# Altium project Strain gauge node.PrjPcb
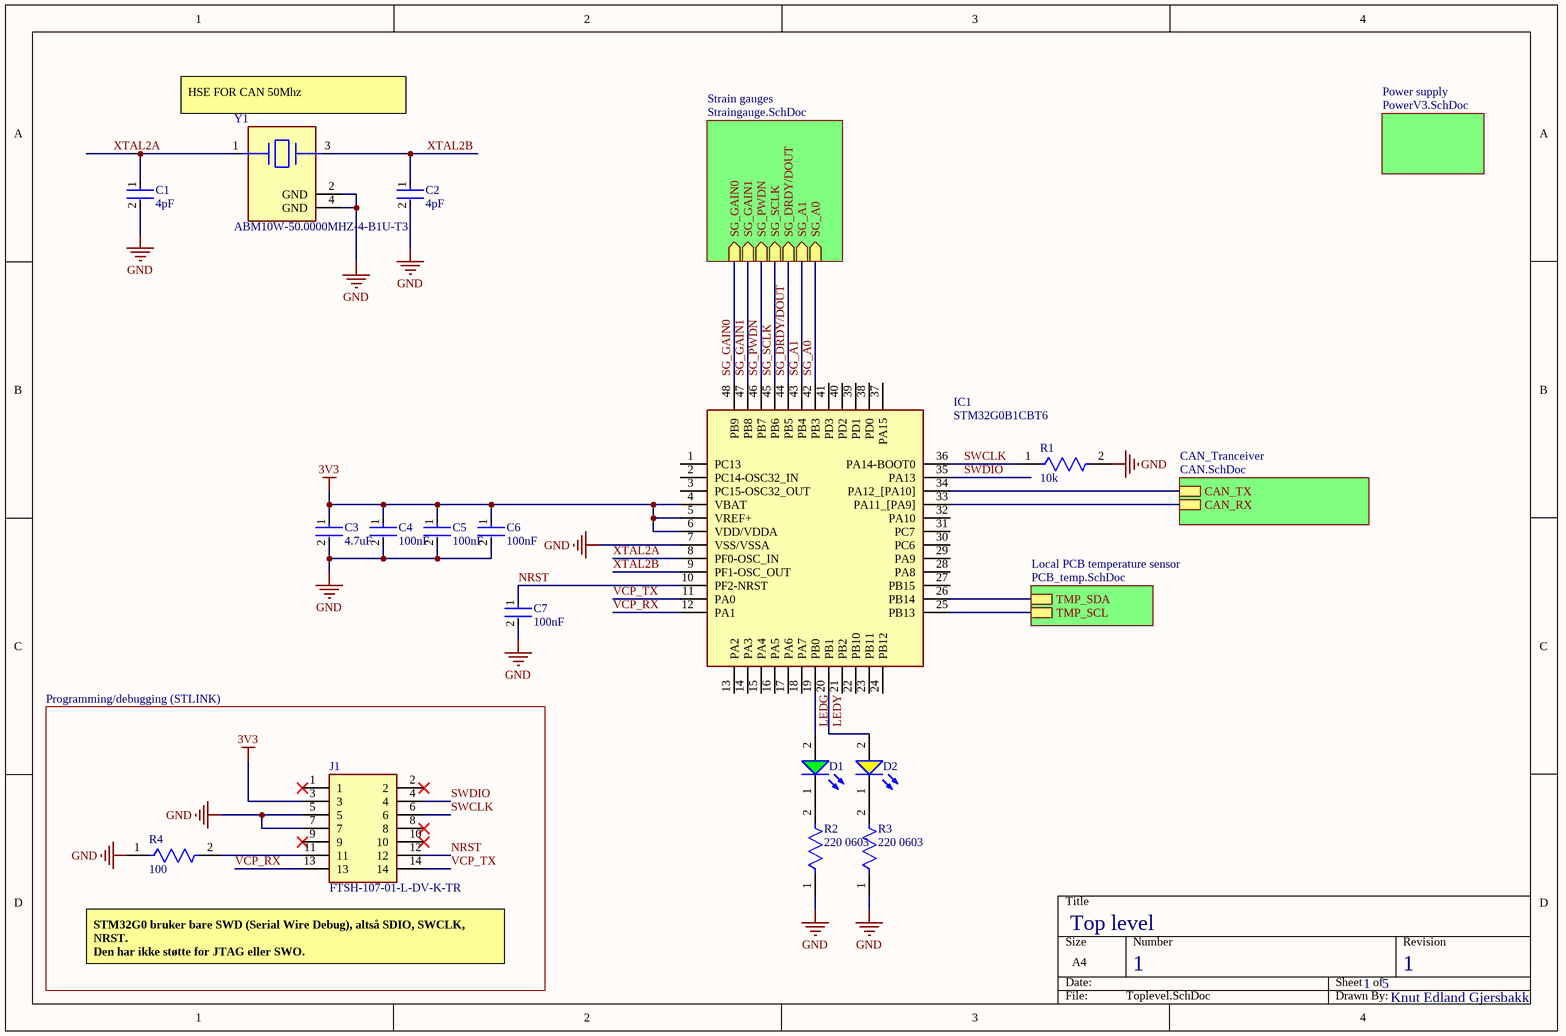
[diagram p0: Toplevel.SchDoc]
5 sheets, 79 parts. Net scope: hierarchical (ports join the sheet entries above them; power ports are global).
Board file: StrainNode.PcbDoc
Sheets:
  Toplevel.SchDoc
    Strain gauges = Straingauge.SchDoc
    Power supply = PowerV3.SchDoc
    CAN_Tranceiver = CAN.SchDoc
    Local PCB temperature sensor = PCB_temp.SchDoc

## Sheet Toplevel.SchDoc
size A4; SheetNumber: 1; SheetTotal: 5

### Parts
C1  4pF  [FP-GQM187-0_15-IPC_B]
C2  4pF  [FP-GQM187-0_15-IPC_B]
C3  4.7uF  [FP-GCM21B-0_15-IPC_A]
C4  100nF  [FP-CL10-IPC_A]
C5  100nF  [FP-CL10-IPC_A]
C6  100nF  [FP-CL10-IPC_A]
C7  100nF  [FP-CL10-IPC_A]
D1  150060GS55040  [WL-SMCD_0603]  (value not drawn)
D2  150060YS75020  [WL-SMCW_0603_150060xx75020]  (value not drawn)
IC1  STM32G0B1CBT6  [QFP50P900X900X160-48N]
J1  FTSH-107-01-L-DV-K-TR  [FTSH10701LDVKTR]
R1  10k  [FP-RT0603-IPC_C]
R2  220 0603  [FP-AF0603-IPC_C]
R3  220 0603  [FP-AF0603-IPC_C]
R4  100  [FP-RT0603-MFG]
Y1  ABM10W-50.0000MHZ-4-B1U-T3  [FP-ABM10W-MFG]

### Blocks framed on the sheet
Programming/debugging (STLINK): J1 R4

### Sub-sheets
CAN_Tranceiver = CAN.SchDoc: CAN_TX, CAN_RX
Local PCB temperature sensor = PCB_temp.SchDoc: TMP_SCL, TMP_SDA
Power supply = PowerV3.SchDoc: no entries
Strain gauges = Straingauge.SchDoc: SG_SCLK (in), SG_DRDY/DOUT (in), SG_PWDN (in), SG_GAIN1 (in), SG_GAIN0 (in), SG_A0 (in), SG_A1 (in)

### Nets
3V3: C3.1 C4.1 C5.1 C6.1 IC1.4(VBAT) IC1.5(VREF+) IC1.6(VDD/VDDA) J1.3
GND: C1.2 C2.2 C3.2 C4.2 C5.2 C6.2 C7.2 IC1.7(VSS/VSSA) J1.5 J1.7 R1.2 R2.1 R3.1 R4.1 Y1.2(GND) Y1.4(GND)
LEDG: D1.2(A) IC1.19(PB0)
LEDY: D2.2(A) IC1.20(PB1)
NRST: C7.1 IC1.10(PF2-NRST) J1.12
SCL: IC1.25(PB13) ; sheet Local PCB temperature sensor/TMP_SCL
SDA: IC1.26(PB14) ; sheet Local PCB temperature sensor/TMP_SDA
SG_A0: IC1.42(PB3) ; sheet Strain gauges/SG_A0
SG_A1: IC1.43(PB4) ; sheet Strain gauges/SG_A1
SG_DRDY/DOUT: IC1.44(PB5) ; sheet Strain gauges/SG_DRDY/DOUT
SG_GAIN0: IC1.48(PB9) ; sheet Strain gauges/SG_GAIN0
SG_GAIN1: IC1.47(PB8) ; sheet Strain gauges/SG_GAIN1
SG_PWDN: IC1.46(PB7) ; sheet Strain gauges/SG_PWDN
SG_SCLK: IC1.45(PB6) ; sheet Strain gauges/SG_SCLK
SWCLK: IC1.36(PA14-BOOT0) J1.6 R1.1
SWDIO: IC1.35(PA13) J1.4
VCP_RX: IC1.12(PA1) J1.13
VCP_TX: IC1.11(PA0) J1.14
XTAL2A: C1.1 IC1.8(PF0-OSC_IN) Y1.1
XTAL2B: C2.1 IC1.9(PF1-OSC_OUT) Y1.3
NetD1_1: D1.1(K) R2.2
NetD2_1: D2.1(K) R3.2
NetIC1_33: IC1.33(PA11_[PA9]) ; sheet CAN_Tranceiver/CAN_RX
NetIC1_34: IC1.34(PA12_[PA10]) ; sheet CAN_Tranceiver/CAN_TX
NetJ1_11: J1.11 R4.2

Not connected (* = marked no-connect by the designer): IC1 1(PC13) 2(PC14-OSC32_IN) 3(PC15-OSC32_OUT) 13(PA2) 14(PA3) 15(PA4) 16(PA5) 17(PA6) 18(PA7) 21(PB2) 22(PB10) 23(PB11) 24(PB12) 27(PB15) 28(PA8) 29(PA9) 30(PC6) 31(PC7) 32(PA10) 37(PA15) 38(PD0) 39(PD1) 40(PD2) 41(PD3); J1 1* 2* 8* 9* 10*

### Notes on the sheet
- (near Y1) HSE FOR CAN 50Mhz
- Top level
- STM32G0 bruker bare SWD (Serial Wire Debug), altså SDIO, SWCLK, NRST.
  Den har ikke støtte for JTAG eller SWO.
- 1
- 5
- Knut Edland Gjersbakk

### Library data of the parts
C1 C2 = CMP-06035-061124-1: GQM1875C2E4R0BB12D / Ceramic Capacitor 4pF ±0.1pF 250VDC C0G 0603 Paper T/R; Voltage Rating: 250V
C3 = CMP-2007-03343-2: Ceramic Capacitor for Automotive 4.7uF ±10% 16VDC X7R 0805 Embossed T/R; Voltage Rating (DC): 16V
C4-C7 = CMP-13271-002683-1: Cap Ceramic 100nF 16V X7R ±10% Pad SMD 0603 +125°C T/R
D1 = CMP-03913-90235563-2: 150060GS55040 WL-SMCD SMT Mono-color Chip LED Diffused; Forward Voltage: 3.2V; Forward Current: 60mA; Luminous Intensity: 430mcd; Peak Wavelength: 520nm; Viewing Angle: 140°; Wavelength: 525nm; Max Reverse Voltage (DC): 5V
D2 = CMP-03913-104891429-2: WL-SMCW SMT Mono-Color Chip LED Waterclear super f; Forward Voltage: 2V; Forward Current: 60mA; Max Reverse Voltage (DC): 5V; Peak Wavelength: 595nm; Viewing Angle: 140°; Dominant Wavelength: 590nm; Luminous Intensity: 130mcd
IC1 = STM32G0B1CBT6: Integrated Circuit; Manufacturer_Name: STMicroelectronics
J1 = FTSH-107-01-L-DV-K-TR: Connector; Manufacturer_Name: SAMTEC
R1 = CMP-03412-005349-1: RES SMD 10K OHM 1% 1/10W 0603 / RT0603FRE0710KL; Manufacturer: Yageo; Value: 10KΩ; Temperature Coefficient: 50 ppm/°C; Power Rating: 0.1W; Tolerance: 0.01; Voltage Rating: 75V
R2 R3 = CMP-03412-038529-1: AF0603JR-07220RL Anti-Sulfurated Chip Resistors Automotive Grade 220Ω 5% 100ppm/°C 0603; Max Power Dissipation: 100mW; Resistance: 220R
R4 = CMP-03412-030646-1: RT0603 100Ω 0.1W 50 ppm/°C 1.00% RT0603FRE07100RL; Manufacturer: Yageo; Manufacturer Part Number: RT0603FRE10100RL; Tolerance: 0.01; Voltage Rating: 75V
Y1 = CMP-27762-007472-1: Crystal 50MHz ±10ppm 4pF SMD-4 2.5mm x 2mm; ESR (Equivalent Series Resistance): 70R

## Sheet Straingauge.SchDoc
size A4; SheetNumber: 2; SheetTotal: 5
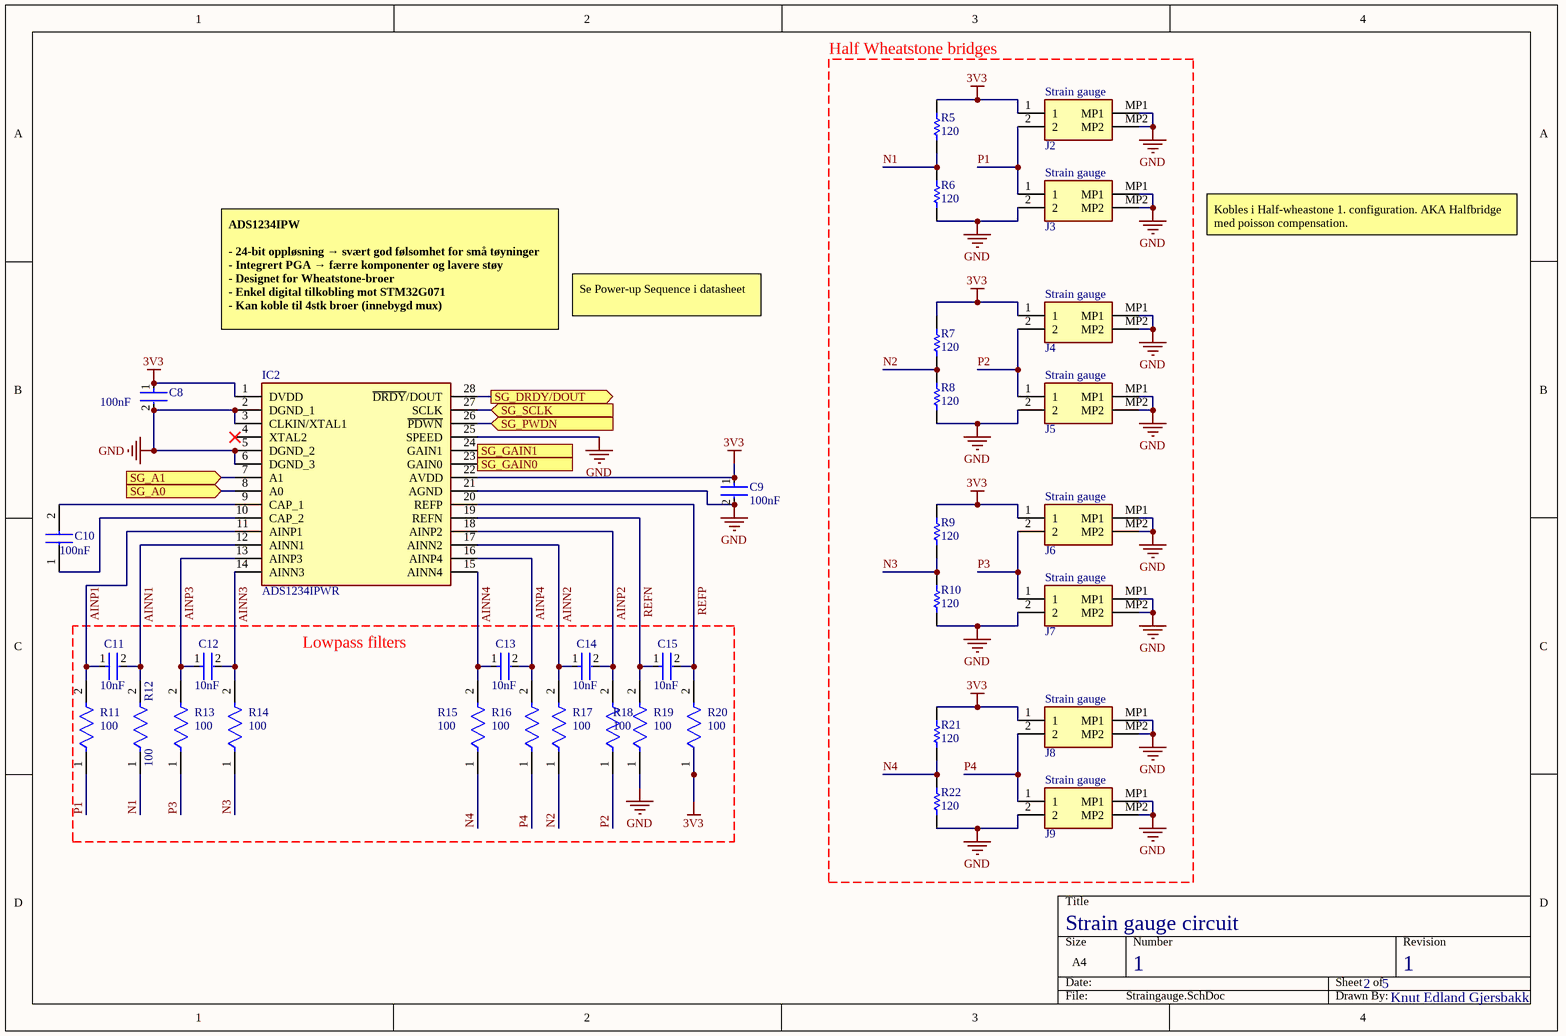
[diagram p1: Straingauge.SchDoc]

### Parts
C8  100nF  [FP-CL10-IPC_C]
C9  100nF  [FP-CL10-IPC_C]
C10  100nF  [CAPC3216X180N]
C11  Capacitance: 10nF  [FP-GRM219-0_1-IPC_B]  (hidden comment: GRM2195C1H103JA01D)
C12  Capacitance: 10nF  [FP-GRM219-0_1-IPC_B]  (hidden comment: GRM2195C1H103JA01D)
C13  Capacitance: 10nF  [FP-GRM219-0_1-IPC_B]  (hidden comment: GRM2195C1H103JA01D)
C14  Capacitance: 10nF  [FP-GRM219-0_1-IPC_B]  (hidden comment: GRM2195C1H103JA01D)
C15  Capacitance: 10nF  [FP-GRM219-0_1-IPC_B]  (hidden comment: GRM2195C1H103JA01D)
IC2  ADS1234IPWR  [SOP65P640X120-28N]
J2  S2B-PH-SM4-TB_LF__SN_  [S2BPHSM4TBLFSN]  (value not drawn)
J3  S2B-PH-SM4-TB_LF__SN_  [S2BPHSM4TBLFSN]  (value not drawn)
J4  S2B-PH-SM4-TB_LF__SN_  [S2BPHSM4TBLFSN]  (value not drawn)
J5  S2B-PH-SM4-TB_LF__SN_  [S2BPHSM4TBLFSN]  (value not drawn)
J6  S2B-PH-SM4-TB_LF__SN_  [S2BPHSM4TBLFSN]  (value not drawn)
J7  S2B-PH-SM4-TB_LF__SN_  [S2BPHSM4TBLFSN]  (value not drawn)
J8  S2B-PH-SM4-TB_LF__SN_  [S2BPHSM4TBLFSN]  (value not drawn)
J9  S2B-PH-SM4-TB_LF__SN_  [S2BPHSM4TBLFSN]  (value not drawn)
R5  120  [RESC2013X60X40ML20T25]
R6  120  [RESC2013X60X40ML20T25]
R7  120  [RESC2013X60X40ML20T25]
R8  120  [RESC2013X60X40ML20T25]
R9  120  [RESC2013X60X40ML20T25]
R10  120  [RESC2013X60X40ML20T25]
R11  100  [FP-ERA3A-IPC_B]
R12  100  [FP-ERA3A-IPC_B]
R13  100  [FP-ERA3A-IPC_B]
R14  100  [FP-ERA3A-IPC_B]
R15  100  [FP-ERA3A-IPC_B]
R16  100  [FP-ERA3A-IPC_B]
R17  100  [FP-ERA3A-IPC_B]
R18  100  [FP-ERA3A-IPC_B]
R19  100  [FP-ERA3A-IPC_B]
R20  100  [FP-ERA3A-IPC_B]
R21  120  [RESC2013X60X40ML20T25]
R22  120  [RESC2013X60X40ML20T25]

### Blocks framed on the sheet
Half Wheatstone bridges: J2-J9 R5-R10 R21 R22
Lowpass filters: C11-C15 R11-R20

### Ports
SG_A0 (in, see Toplevel[3B]), SG_A1 (in, see Toplevel[3B]), SG_DRDY/DOUT (out, see Toplevel[3B]), SG_GAIN0 (in, see Toplevel[2B]), SG_GAIN1 (in, see Toplevel[2B]), SG_PWDN (in, see Toplevel[2B]), SG_SCLK (in, see Toplevel[2B])

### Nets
3V3: C8.1 C9.1 IC2.1(DVDD) IC2.22(AVDD) J2.1 J4.1 J6.1 J8.1 R5.2 R7.2 R9.2 R20.1 R21.2
GND: C8.2 C9.2 IC2.2(DGND_1) IC2.3(CLKIN/XTAL1) IC2.5(DGND_2) IC2.6(DGND_3) IC2.21(AGND) IC2.25(SPEED) J2.MP1 J2.MP2 J3.2 J3.MP1 J3.MP2 J4.MP1 J4.MP2 J5.2 J5.MP1 J5.MP2 J6.MP1 J6.MP2 J7.2 J7.MP1 J7.MP2 J8.MP1 J8.MP2 J9.2 J9.MP1 J9.MP2 R6.1 R8.1 R10.1 R19.1 R22.1
AINN1: C11.2 IC2.12(AINN1) R12.2
AINN2: C14.1 IC2.17(AINN2) R17.2
AINN3: C12.2 IC2.14(AINN3) R14.2
AINN4: C13.1 IC2.15(AINN4) R15.2
AINP1: C11.1 IC2.11(AINP1) R11.2
AINP2: C14.2 IC2.18(AINP2) R18.2
AINP3: C12.1 IC2.13(AINP3) R13.2
AINP4: C13.2 IC2.16(AINP4) R16.2
N1: R5.1 R6.2 R12.1
N2: R7.1 R8.2 R17.1
N3: R9.1 R10.2 R14.1
N4: R15.1 R21.1 R22.2
P1: J2.2 J3.1 R11.1
P2: J4.2 J5.1 R18.1
P3: J6.2 J7.1 R13.1
P4: J8.2 J9.1 R16.1
REFN: C15.1 IC2.19(REFN) R19.2
REFP: C15.2 IC2.20(REFP) R20.2
SG_A0: IC2.8(A0) ; port SG_A0
SG_A1: IC2.7(A1) ; port SG_A1
SG_DRDY/DOUT: IC2.28(~{DRDY}/DOUT) ; port SG_DRDY/DOUT
SG_GAIN0: IC2.23(GAIN0) ; port SG_GAIN0
SG_GAIN1: IC2.24(GAIN1) ; port SG_GAIN1
SG_PWDN: IC2.26(~{PDWN}) ; port SG_PWDN
SG_SCLK: IC2.27(SCLK) ; port SG_SCLK
NetC10_1: C10.1 IC2.10(CAP_2)
NetC10_2: C10.2 IC2.9(CAP_1)

Not connected (* = marked no-connect by the designer): IC2 4(XTAL2)*

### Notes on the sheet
- (near J2) Strain gauge
- (near J3) Strain gauge
- Kobles i Half-wheastone 1. configuration. AKA Halfbridge med poisson compensation.
- Se Power-up Sequence i datasheet
- (near J4) Strain gauge
- ADS1234IPW
  - 24-bit oppløsning → svært god følsomhet for små tøyninger
  - Integrert PGA → færre komponenter og lavere støy
  - Designet for Wheatstone-broer
  - Enkel digital tilkobling mot STM32G071
  - Kan koble til 4stk broer (innebygd mux)
  Gain bør settes til 64 for Half bridge
- (near J5) Strain gauge
- (near J6) Strain gauge
- (near J7) Strain gauge
- (near J8) Strain gauge
- (near J9) Strain gauge
- Strain gauge circuit
- 1
- 2
- 5
- Knut Edland Gjersbakk

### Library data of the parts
C8 C9 = CMP-13271-002683-1: Cap Ceramic 100nF 16V X7R ±10% Pad SMD 0603 +125°C T/R / CL10B104KO8WPNC
C10 = GRM31C5C1E104JA01L: Capacitor; Manufacturer_Name: Murata Electronics
C11-C15 = CMP-2007-00135-2: Chip Multilayer Ceramic Capacitors for General Purpose, 0805, 10000pF, C0G, 30ppm/°C, 5%, 50V; Insulation Resistance: 10GR
IC2 = ADS1234IPWR: Integrated Circuit; Manufacturer_Name: Texas Instruments
J2-J9 = S2B-PH-SM4-TB_LF__SN_: Connector; Manufacturer_Name: JST (JAPAN SOLDERLESS TERMINALS); Manufacturer_Part_Number: S2B-PH-SM4-TB(LF)(SN)
R5-R10 R21 R22 = CMP-2001-00588-1: Manufacturer: Panasonic; Part Number: ERA6AEB121V
R11-R20 = CMP-2000-00870-2: RES SMD 100 OHM 0.1% 1/10W 0603; Voltage Rating: 75V; Power Rating: 100mW; Resistance: 100R; Temperature Coefficient: 25ppm/°C

## Sheet PowerV3.SchDoc
size A3; SheetNumber: 4; SheetTotal: 5
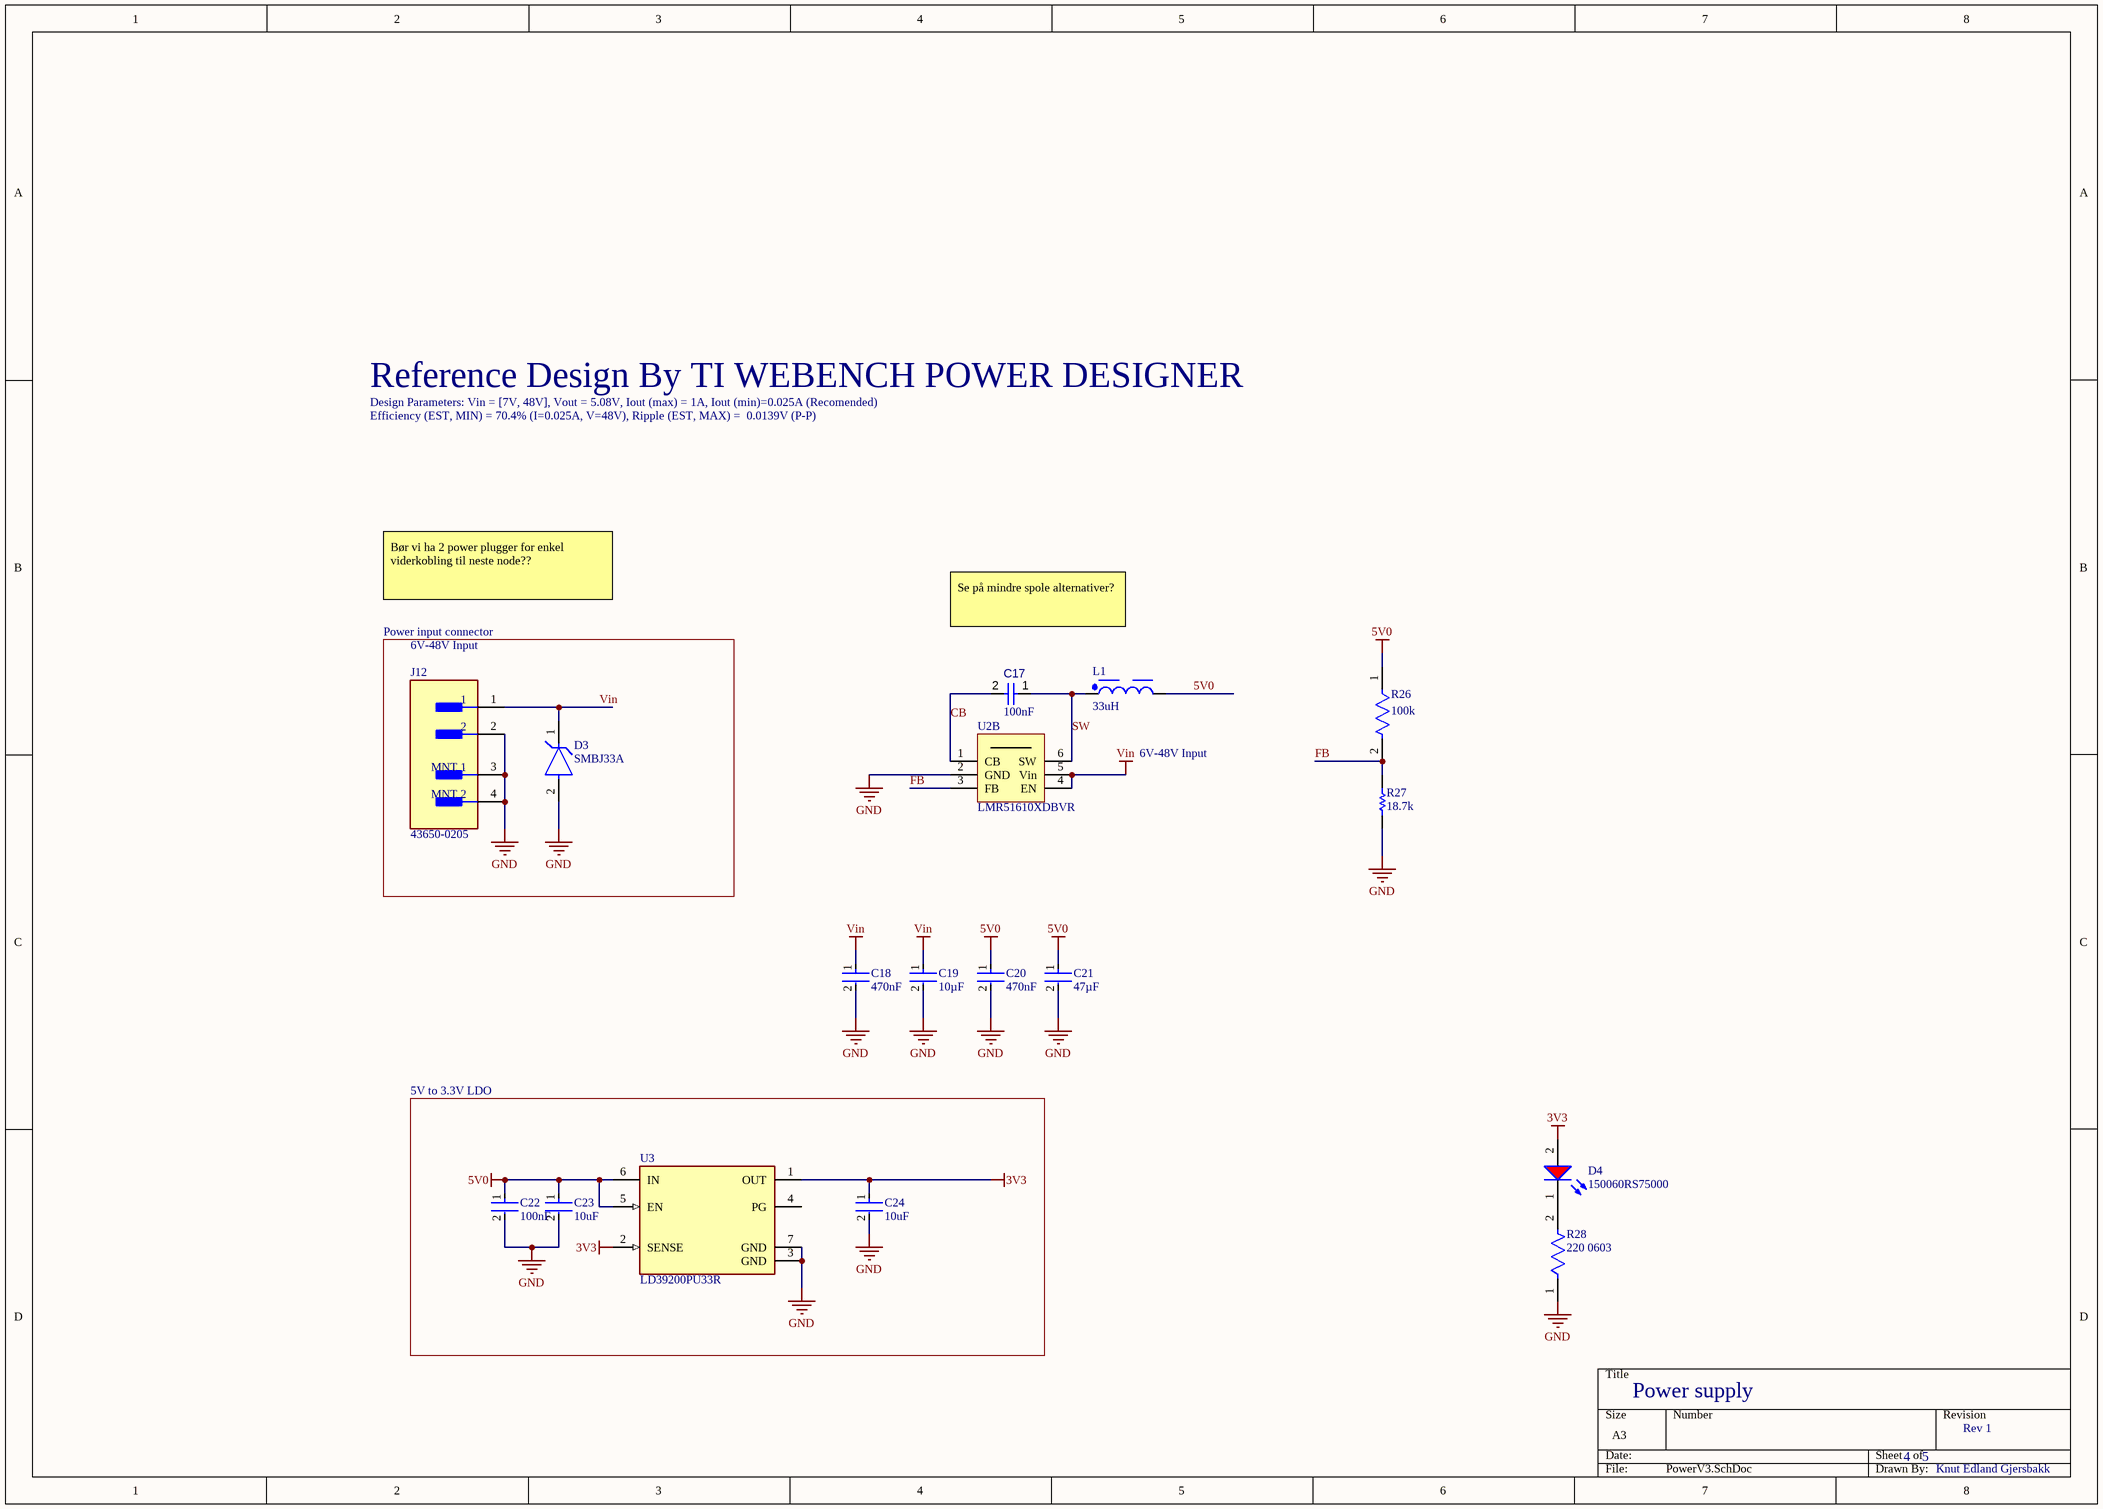
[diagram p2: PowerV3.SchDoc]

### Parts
C17  value 100nF  [CAPC2013X95X50LL10T25]  (hidden comment: Capacitor 100 nF +/-10% 50 V 0805)
C18  value 470nF  [FP-CL21-IPC_A]  (hidden comment: CL21B474KBFNNNF)
C19  value 10µF  [FP-CL31B106KBHNNNE-IPC_A]  (hidden comment: CL31B106KBHNNNE)
C20  value 470nF  [FP-CL21-IPC_A]  (hidden comment: CL21B474KBFNNNF)
C21  value 47µF  [FP-GRM31C-0_2-e0_3_0_8-IPC_B]  (hidden comment: GRM31CR61A476KE15K)
C22  100nF  [FP-CL10-IPC_C]
C23  10uF  [FP-CL10-IPC_C]
C24  10uF  [FP-CL10-IPC_C]
D3  SMBJ33A  [FP-SMBJ-MFG]
D4  150060RS75000  [WL-SMCW_0603_150060xx75000]
J12  43650-0205  [FP-43650-0205-MFG]
L1  value 33uH  [WE-PD_1260P]  (hidden comment: 7447706330)
R26  value 100k  [FP-CRGCQ1206-IPC_A]  (hidden comment: CRGCQ1206F100K)
R27  value 18.7k  [RESC2013X60X40LL20T25]  (hidden comment: ERA-6AEB1872V)
R28  220 0603  [FP-AF0603-IPC_C]
U2  LMR51610XDBVR  [SOT95P280X145-6N]  (part B of 2)
U3  LD39200PU33R  [FP-DFN6-7946637-MFG]

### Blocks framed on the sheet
5V to 3.3V LDO: C22-C24 U3

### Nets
3V3: C24.1 D4.2(A) U3.1(OUT) U3.2(SENSE)
5V0: C20.1 C21.1 C22.1 C23.1 L1.2 R26.1 U3.5(EN) U3.6(IN)
GND: C18.2 C19.2 C20.2 C21.2 C22.2 C23.2 C24.2 D3.2(A) J12.2 J12.3(MNT_1) J12.4(MNT_2) R27.2 R28.1 U2.2(GND) U3.3(GND) U3.7(GND)
Vin: C18.1 C19.1 D3.1(C) J12.1 U2.4(EN) U2.5(Vin)
CB: C17.2 U2.1(CB)
FB: R26.2 R27.1 U2.3(FB)
SW: C17.1 L1.1 U2.6(SW)
NetD4_1: D4.1(K) R28.2

Not connected (* = marked no-connect by the designer): U3 4(PG)

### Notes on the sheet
- Reference Design By TI WEBENCH POWER DESIGNER
- Design Parameters: Vin = [7V, 48V], Vout = 5.08V, Iout (max) = 1A, Iout (min)=0.025A (Recomended)
- Efficiency (EST, MIN) = 70.4% (I=0.025A, V=48V), Ripple (EST, MAX) =  0.0139V (P-P)
- Power input connector
- Bør vi ha 2 power plugger for enkel viderkobling til neste node??
- 6V-48V Input
- Se på mindre spole alternativer?
- Power supply
- 4
- 5
- Rev 1
- Knut Edland Gjersbakk

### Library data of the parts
C17 = CMP-001-00018-6: Chip Capacitor, 100 nF, +/- 10%, 50 V, 0805 (2012 Metric); Capacitor Type: Ceramic; Voltage Rating: 50V
C18 C20 = CMP-001-00098-1: Ceramic Capacitor, Multilayer, Ceramic, 50V, 10% +Tol, 10% -Tol, X7R, 15% TC, 0.47uF, Surface Mount, 0805; Multilayer: Yes
C19 = CMP-001-00099-1: Ceramic Capacitor, Multilayer, Ceramic, 50V, 10% +Tol, 10% -Tol, X7R, 15% TC, 10uF, Surface Mount, 1206; Multilayer: Yes
C21 = CMP-001-00103-1: Ceramic Capacitor, Multilayer, Ceramic, 10V, 10% +Tol, 10% -Tol, X5R, 15% TC, 47uF, Surface Mount, 1206; Multilayer: Yes
C22 = CMP-13271-002683-1: as C8 on sheet Straingauge
C23 C24 = CMP-13271-003287-1: Cap Ceramic 10uF 16V X6S ±20% Pad SMD 0603 +105°C T/R / CL10X106MO8NRNC
D3 = CMP-2000-07095-2: TVS DIODE 33V 53.3V DO214AA; Manufacturer: Littelfuse Inc; Max Junction Temp: +150°C; Number Of Channels: 1; Breakdown Voltage: 36.7V; Peak Pulse Power: 600W; Direction: Unidirectional; Peak Pulse Current: 11.3A
D4 = CMP-1426-00001-4: LED Low-Power Uni-Color Red 630nm 2V 2-Pin Chip 0603(1608Metric) T/R; Max Junction Temperature (Tj): 95°C; Dominant Wavelength: 625nm; Lens Style: Clear, Rectangular; Viewing Angle: 140°; Forward Current: 100mA; Max Reverse Voltage (DC): 5V; Luminous Intensity: 250mcd; Test Current: 20mA; Power Dissipation: 72mW
J12 = CMP-00257-07672643-1: 43650-0205 Conn Wire to Board HDR 2 POS 3mm Solder RA Side Entry Thru-Hole Micro-Fit 3.0™ Tray; Manufacturer Lifecycle Status: ACTIVE; Plating: Tin; Glow Wire Compliant: Compliant; Number of Contacts: 2; Gender: Male; Voltage Rating: 600V; Current Rating: 5A
L1 = CMP-006-00028-1: General Purpose Inductor
R26 = CMP-009-00192-1: Fixed Resistor, Metal Glaze/thick Film, 0.25W, 100000ohm, 200V, 1% +/-Tol, 100ppm/Cel, Surface Mount, 1206
R27 = CMP-009-00195-1: Fixed Resistor, Thin Film, 0.125W, 18700ohm, 100V, 0.1% +/-Tol, 25ppm/Cel, Surface Mount, 0805; Rated Temperature: 85°C; Temperature Coefficient (ppm/Cel): 25; Reference Standard: AEC-Q200; Package Width: 1.25mm; Package Length: 2mm; Package Height: 0.5mm; Power: 125mW
R28 = CMP-03412-038529-1: as R2 on sheet Toplevel
U2 = CMP-019-00059-1: SIMPLE SWITCHER® 4.5-V to 65-V, 1-A synchronous buck converter with 25-µA IQ 6-SOT-23 -40 to 150; Max Supply Voltage: 65V; Min Supply Voltage: 4.5V; Output Current: 1A; Frequency: 400Hz
U3 = CMP-12153-000011-1: IC REG LINEAR 3.3V 2A 6DFN; Number of Outputs: 1; Max Input Voltage: 6V; Output Type: Fixed; Min Input Voltage: 1.25V; Dropout Voltage: 130mV; Operating Supply Current: 1mA

## Sheet CAN.SchDoc
size A4; SheetNumber: 3; SheetTotal: 5
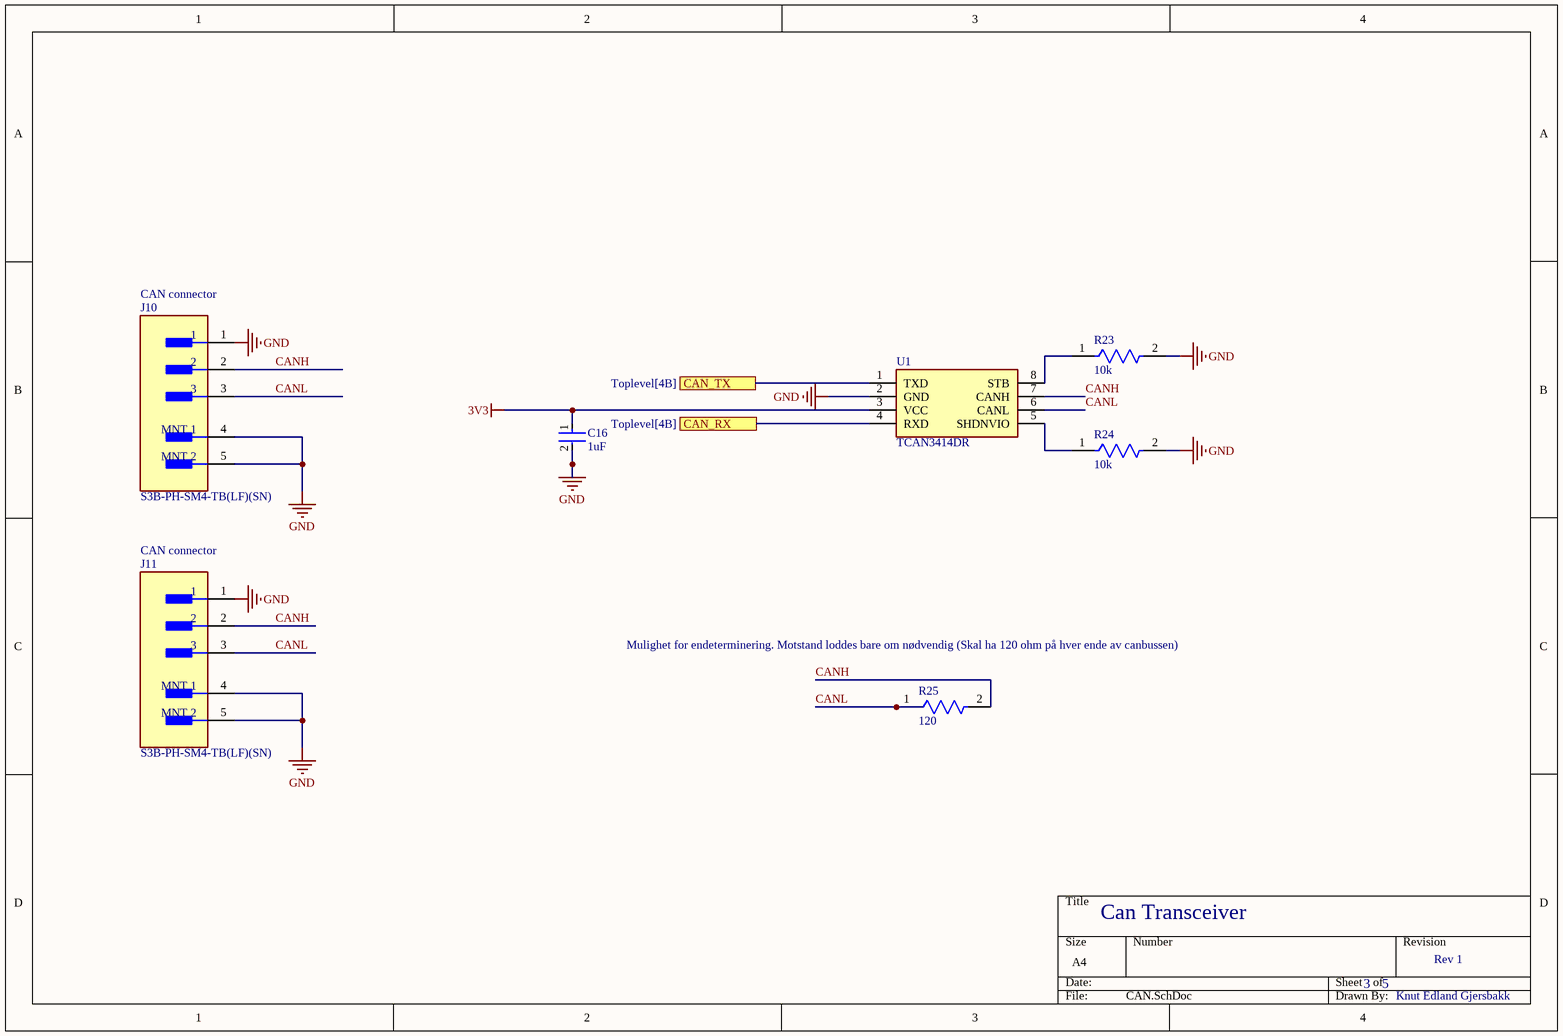
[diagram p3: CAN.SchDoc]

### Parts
C16  1uF  [FP-CL10-IPC_C]
J10  S3B-PH-SM4-TB(LF)(SN)  [FP-S3B-PH-SM4-TB_LF_SN-MFG]
J11  S3B-PH-SM4-TB(LF)(SN)  [FP-S3B-PH-SM4-TB_LF_SN-MFG]
R23  10k  [FP-RT0603-IPC_C]
R24  10k  [FP-RT0603-IPC_C]
R25  120  [FP-AF0603-IPC_C]
U1  TCAN3414DR  [SOIC127P600X175-8N]

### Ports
CAN_RX (see Toplevel[4B]), CAN_TX (see Toplevel[4B])

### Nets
3V3: C16.1 U1.3(VCC)
GND: C16.2 J10.1 J10.4(MNT_1) J10.5(MNT_2) J11.1 J11.4(MNT_1) J11.5(MNT_2) R23.2 R24.2 U1.2(GND)
CANH: J10.2 J11.2 R25.2 U1.7(CANH)
CANL: J10.3 J11.3 R25.1 U1.6(CANL)
NetIC1_33: U1.4(RXD) ; port CAN_RX
NetIC1_34: U1.1(TXD) ; port CAN_TX
NetR23_1: R23.1 U1.8(STB)
NetR24_1: R24.1 U1.5(SHDNVIO)

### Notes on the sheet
- (near J10) CAN connector
- (near J11) CAN connector
- Mulighet for endeterminering. Motstand loddes bare om nødvendig (Skal ha 120 ohm på hver ende av canbussen)
- Can Transceiver
- 3
- 5
- Rev 1
- Knut Edland Gjersbakk

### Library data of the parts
C16 = CMP-13271-000784-1: Cap Ceramic 1uF 16V X7R ±10% Pad SMD 0603 +125°C T/R / CL10B105KO8NNNL
J10 J11 = CMP-002-00113-1: Connector Header, PH Series, 3 Position, Side Entry, 2.00mm, Solder, Surface Mount, Natural.; Voltage Rating: 100V; Max Current Rating: 2A; Connector Type: Male Pin; Gender: Male
R23 R24 = CMP-03412-005349-1: as R1 on sheet Toplevel
R25 = CMP-03412-039700-1: Anti-Sulfurated Chip Resistors Automotive Grade 120Ω 1% 100ppm/°C 0603 AF0603FR-07120RL; Max Power Dissipation: 100mW; Resistance: 120R
U1 = TCAN3414DR: Integrated Circuit; Manufacturer_Name: Texas Instruments

## Sheet PCB_temp.SchDoc
size A4; SheetNumber: 5; SheetTotal: 5
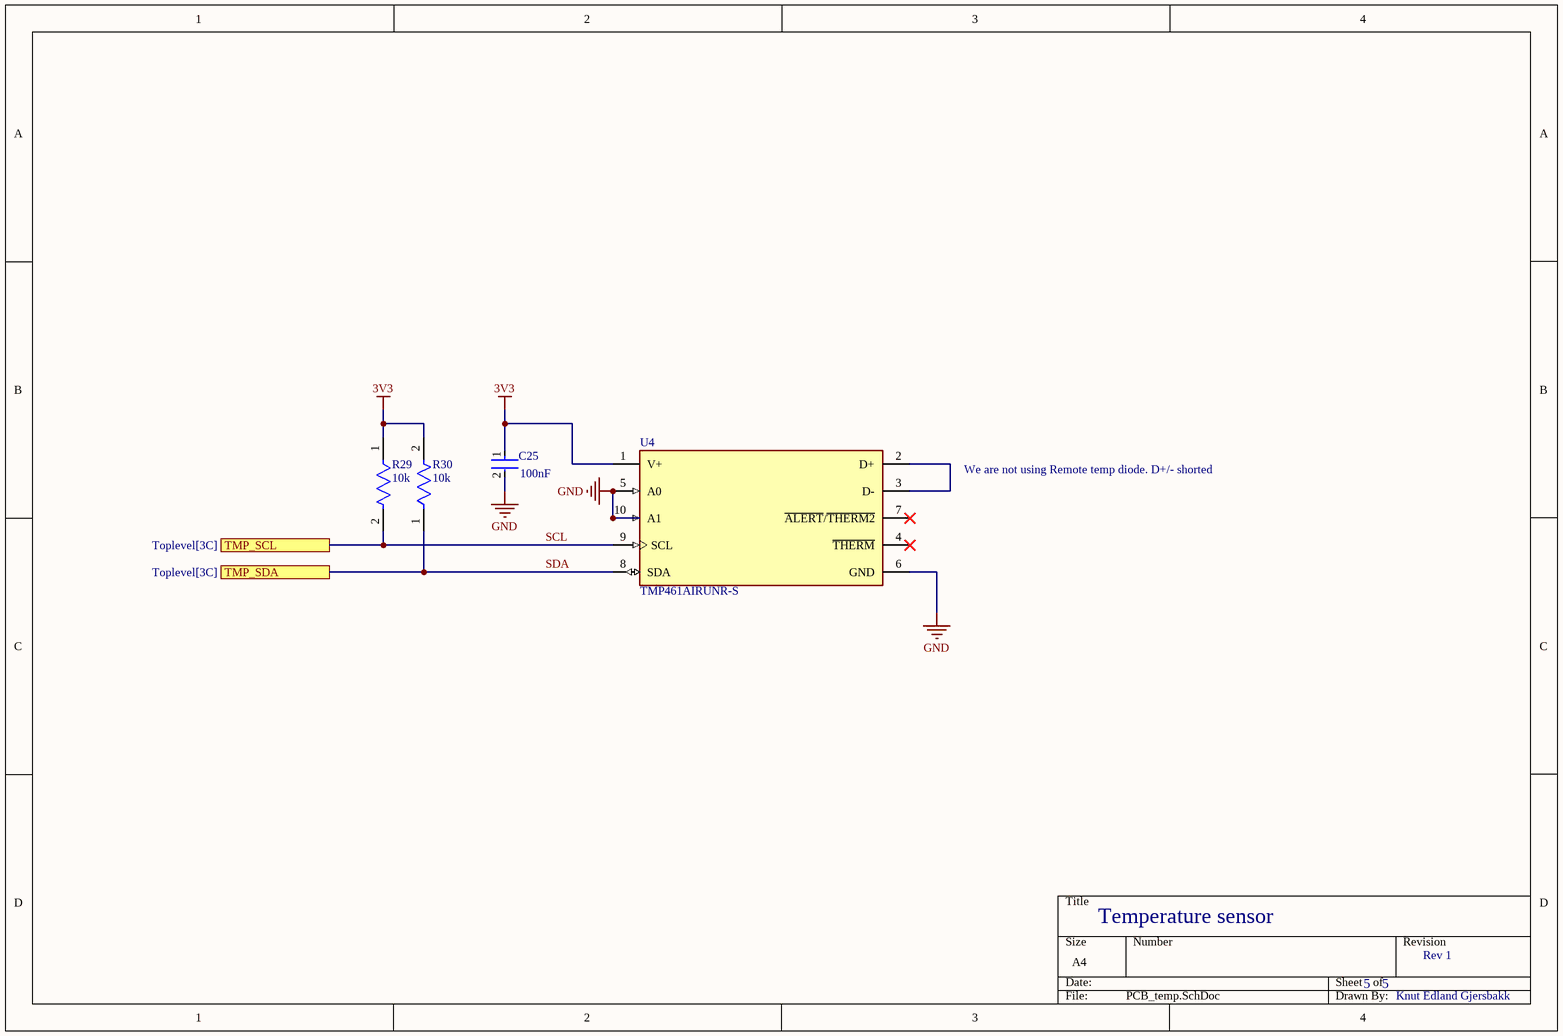
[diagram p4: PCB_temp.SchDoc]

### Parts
C25  100nF  [FP-CL10-IPC_A]
R29  10k  [FP-RT0603-IPC_C]
R30  10k  [FP-RT0603-IPC_C]
U4  TMP461AIRUNR-S  [FP-RUN0010A-MFG]

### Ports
TMP_SCL (see Toplevel[3C]), TMP_SDA (see Toplevel[3C])

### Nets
3V3: C25.1 R29.1 R30.2 U4.1(V+)
GND: C25.2 U4.5(A0) U4.6(GND) U4.10(A1)
SCL: R29.2 U4.9(SCL) ; port TMP_SCL
SDA: R30.1 U4.8(SDA) ; port TMP_SDA
NetU4_2: U4.2(D+) U4.3(D-)

Not connected (* = marked no-connect by the designer): U4 4(~{THERM})* 7(~{ALERT}/~{THERM2})*

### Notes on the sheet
- We are not using Remote temp diode. D+/- shorted
- Temperature sensor
- 5
- Rev 1
- Knut Edland Gjersbakk

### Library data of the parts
C25 = CMP-13271-002683-1: as C4 on sheet Toplevel
R29 R30 = CMP-03412-005349-1: as R1 on sheet Toplevel
U4 = CMP-00370-103943066-1: TMP461AIRUNR-S Temperature Sensor Digital, Local/Remote -40°C ~ 125°C 11 b 10-WQFN (2x2); Manufacturer Lifecycle Status: ACTIVE

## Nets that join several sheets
3V3: Toplevel (8 pins), Straingauge (13 pins), PowerV3 (C24.1 D4.2 U3.1 U3.2), CAN (C16.1 U1.3), PCB_temp (C25.1 R29.1 R30.2 U4.1)
GND: Toplevel (16 pins), Straingauge (33 pins), PowerV3 (16 pins), CAN (10 pins), PCB_temp (C25.2 U4.5 U4.6 U4.10)
NetIC1_33: Toplevel (IC1.33), CAN (U1.4)
NetIC1_34: Toplevel (IC1.34), CAN (U1.1)
SCL: Toplevel (IC1.25), PCB_temp (R29.2 U4.9)
SDA: Toplevel (IC1.26), PCB_temp (R30.1 U4.8)
SG_A0: Toplevel (IC1.42), Straingauge (IC2.8)
SG_A1: Toplevel (IC1.43), Straingauge (IC2.7)
SG_DRDY/DOUT: Toplevel (IC1.44), Straingauge (IC2.28)
SG_GAIN0: Toplevel (IC1.48), Straingauge (IC2.23)
SG_GAIN1: Toplevel (IC1.47), Straingauge (IC2.24)
SG_PWDN: Toplevel (IC1.46), Straingauge (IC2.26)
SG_SCLK: Toplevel (IC1.45), Straingauge (IC2.27)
